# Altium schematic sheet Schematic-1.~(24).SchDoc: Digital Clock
size A3; Author: DENANATH S; DrawnBy: DENANATH; Revision: 1; SheetNumber: 1; SheetTotal: 1
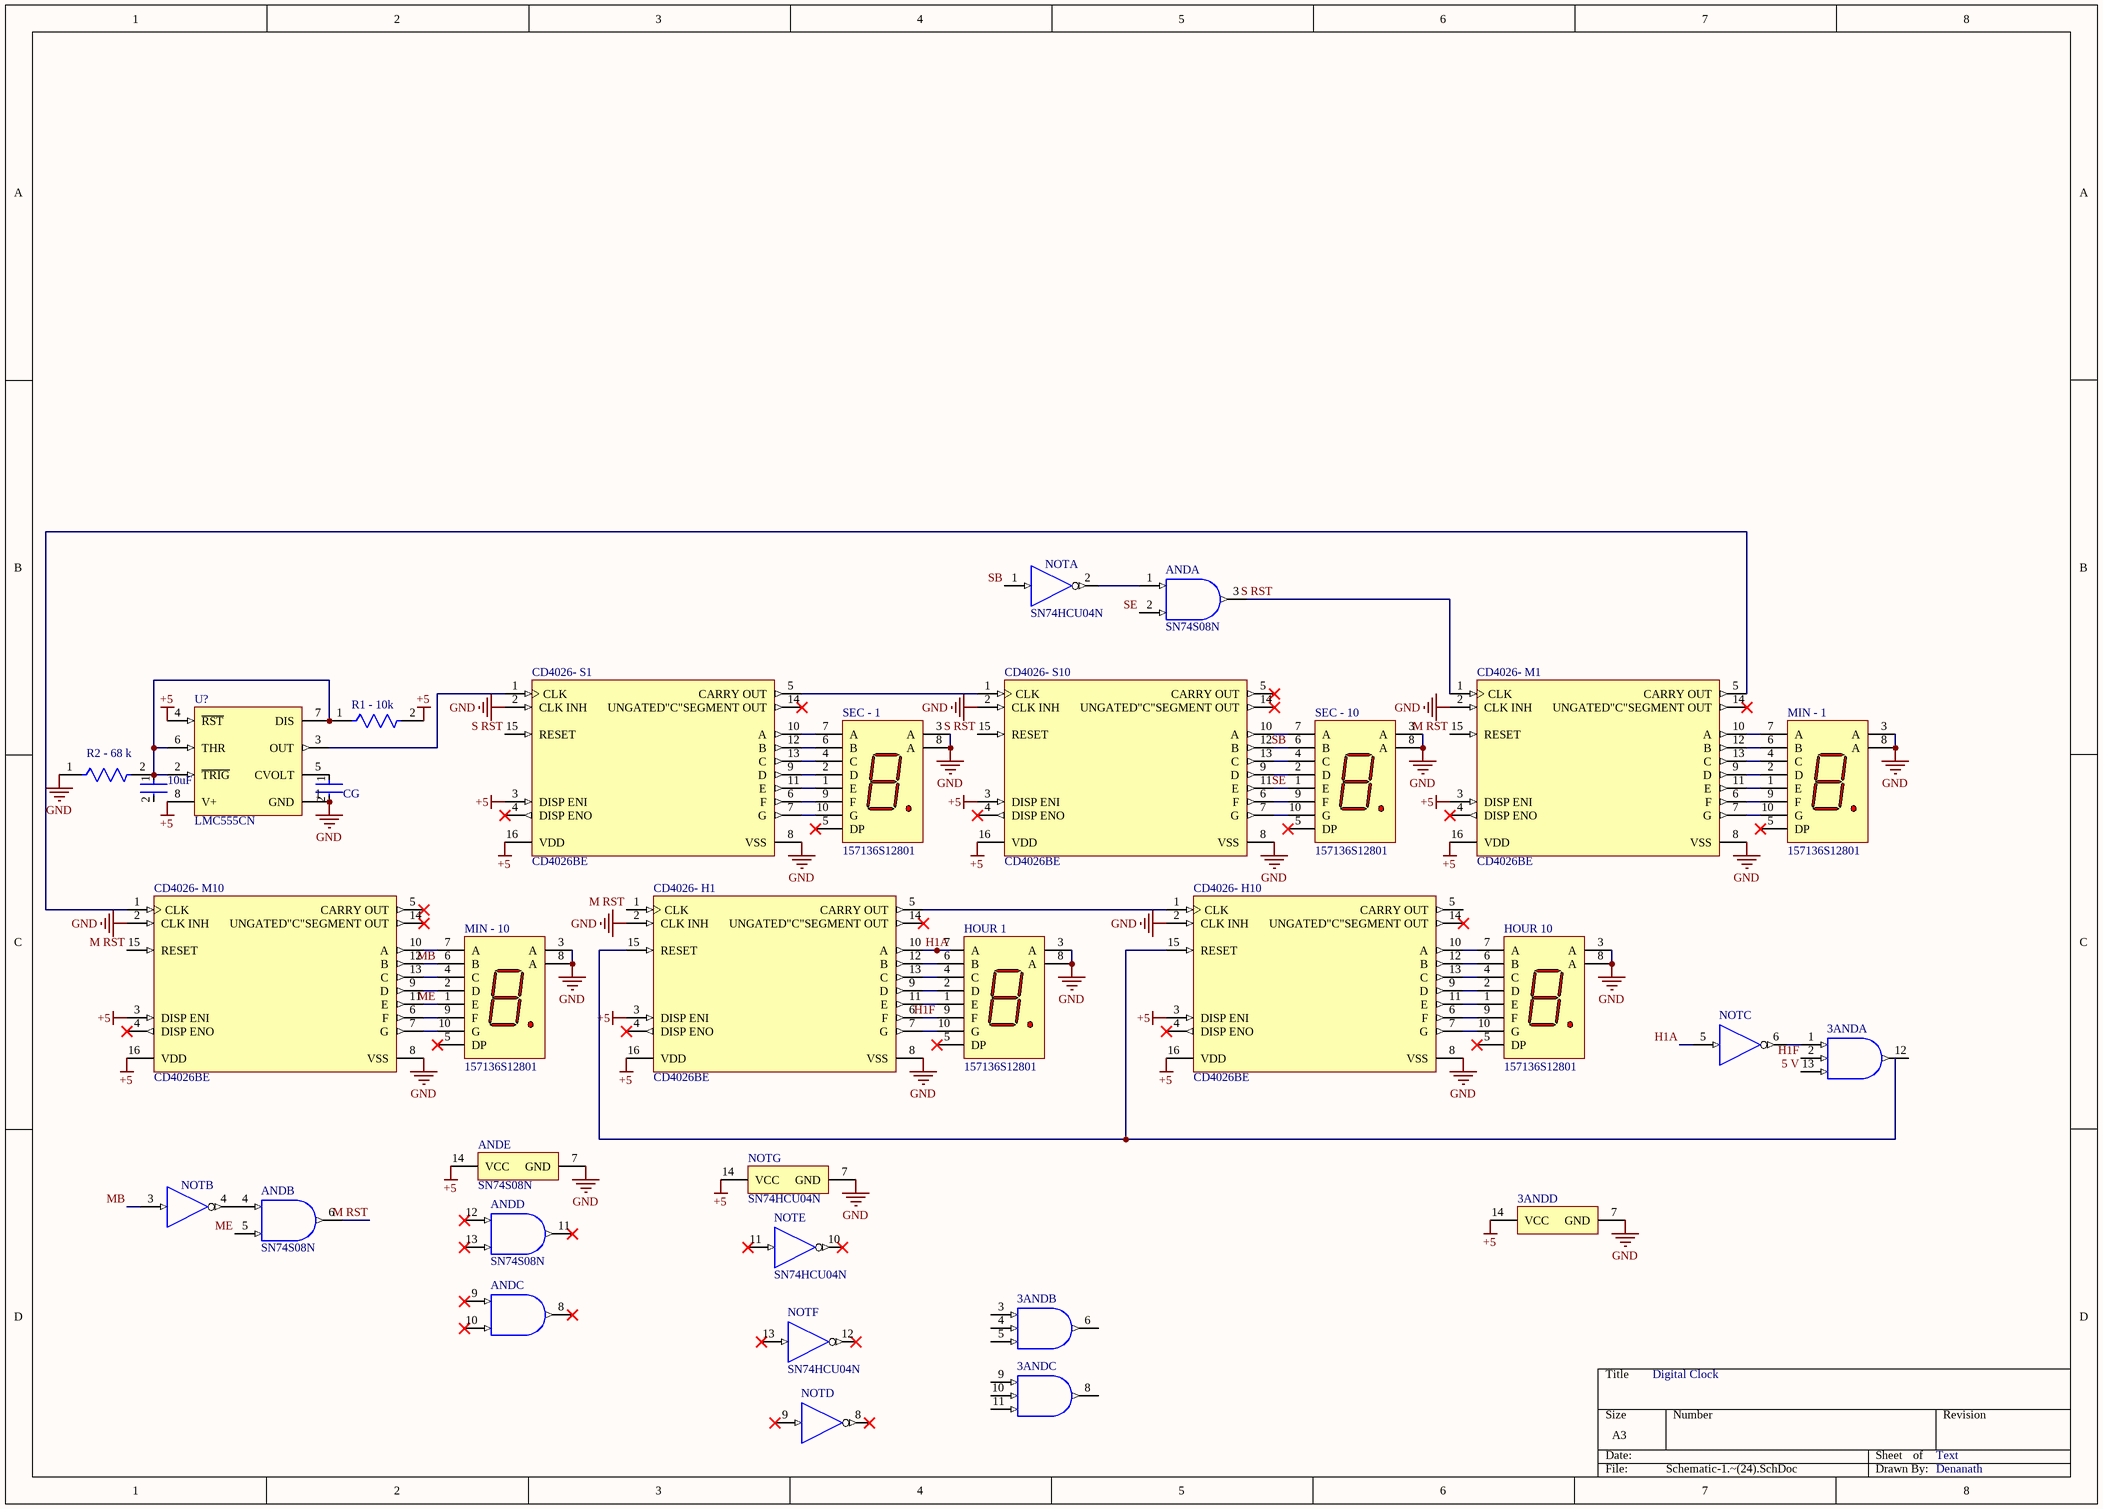
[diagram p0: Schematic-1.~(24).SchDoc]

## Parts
3AND  SN74LS11N  [N0014A]  (value not drawn)  (parts A,B,C,D of 4)
10uF  VY1472M63Y5UQ6TV0  [FP-VY1472M63Y5UQ6TV0-MFG]  (value not drawn)
AND  SN74S08N  [N0014A]  (parts A,B,C,D,E of 5)
CD4026-_H1  CD4026BE  [N0016A]
CD4026-_H10  CD4026BE  [N0016A]
CD4026-_M1  CD4026BE  [N0016A]
CD4026-_M10  CD4026BE  [N0016A]
CD4026-_S1  CD4026BE  [N0016A]
CD4026-_S10  CD4026BE  [N0016A]
CG  VY1472M63Y5UQ6TV0  [FP-VY1472M63Y5UQ6TV0-MFG]  (value not drawn)
HOUR_1  157136S12801  [WL-T7DS_L17.5W12.4H7]
HOUR_10  157136S12801  [WL-T7DS_L17.5W12.4H7]
MIN_-_1  157136S12801  [WL-T7DS_L17.5W12.4H7]
MIN_-_10  157136S12801  [WL-T7DS_L17.5W12.4H7]
NOT  SN74HCU04N  [N0014A]  (parts A,B,C,D,E,F,G of 7)
R1_-_10k  VR37000001204JA100  [FP-VR37-MFG]  (value not drawn)
R2_-_68_k  VR37000001204JA100  [FP-VR37-MFG]  (value not drawn)
SEC_-_1  157136S12801  [WL-T7DS_L17.5W12.4H7]
SEC_-_10  157136S12801  [WL-T7DS_L17.5W12.4H7]
U?  LMC555CN  [P0008A]

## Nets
+5: 3AND.14(VCC) AND.14(VCC) CD4026-_H1.3(DISP_ENI) CD4026-_H1.16(VDD) CD4026-_H10.3(DISP_ENI) CD4026-_H10.16(VDD) CD4026-_M1.3(DISP_ENI) CD4026-_M1.16(VDD) CD4026-_M10.3(DISP_ENI) CD4026-_M10.16(VDD) CD4026-_S1.3(DISP_ENI) CD4026-_S1.16(VDD) CD4026-_S10.3(DISP_ENI) CD4026-_S10.16(VDD) NOT.14(VCC) R1_-_10k.2 U?.4(~{RST}) U?.8(V+)
GND: 3AND.7(GND) AND.7(GND) CD4026-_H1.2(CLK_INH) CD4026-_H1.8(VSS) CD4026-_H10.2(CLK_INH) CD4026-_H10.8(VSS) CD4026-_M1.2(CLK_INH) CD4026-_M1.8(VSS) CD4026-_M10.2(CLK_INH) CD4026-_M10.8(VSS) CD4026-_S1.2(CLK_INH) CD4026-_S1.8(VSS) CD4026-_S10.2(CLK_INH) CD4026-_S10.8(VSS) CG.2 HOUR_1.3(A) HOUR_1.8(A) HOUR_10.3(A) HOUR_10.8(A) MIN_-_1.3(A) MIN_-_1.8(A) MIN_-_10.3(A) MIN_-_10.8(A) NOT.7(GND) R2_-_68_k.1 SEC_-_1.3(A) SEC_-_1.8(A) SEC_-_10.3(A) SEC_-_10.8(A) U?.1(GND)
5 V: 3AND.13(1C)
H1A: CD4026-_H1.10(A) HOUR_1.7(A) NOT.5(3A)
H1F: 3AND.2(1B) CD4026-_H1.6(F) HOUR_1.9(F)
M RST: AND.6(2Y) CD4026-_H1.1(CLK) CD4026-_M1.15(RESET) CD4026-_M10.15(RESET)
MB: CD4026-_M10.12(B) MIN_-_10.6(B) NOT.3(2A)
ME: AND.5(2B) CD4026-_M10.11(E) MIN_-_10.1(E)
S RST: AND.3(1Y) CD4026-_M1.1(CLK) CD4026-_S1.15(RESET) CD4026-_S10.15(RESET)
SB: CD4026-_S10.12(B) NOT.1(1A) SEC_-_10.6(B)
SE: AND.2(1B) CD4026-_S10.11(E) SEC_-_10.1(E)
Net3AND_1: 3AND.1(1A) NOT.6(~{3Y})
Net10uF_1: 10uF.1 R1_-_10k.1 R2_-_68_k.2 U?.2(~{TRIG}) U?.6(THR) U?.7(DIS)
NetAND_1: AND.1(1A) NOT.2(~{1Y})
NetAND_4: AND.4(2A) NOT.4(~{2Y})
NetCD4026-_H1_5: CD4026-_H1.5(CARRY_OUT) CD4026-_H10.1(CLK)
NetCD4026-_H1_7: CD4026-_H1.7(G) HOUR_1.10(G)
NetCD4026-_H1_9: CD4026-_H1.9(D) HOUR_1.2(D)
NetCD4026-_H1_11: CD4026-_H1.11(E) HOUR_1.1(E)
NetCD4026-_H1_12: CD4026-_H1.12(B) HOUR_1.6(B)
NetCD4026-_H1_13: CD4026-_H1.13(C) HOUR_1.4(C)
NetCD4026-_H1_15: CD4026-_H1.15(RESET) CD4026-_H10.15(RESET)
NetCD4026-_H10_6: CD4026-_H10.6(F) HOUR_10.9(F)
NetCD4026-_H10_7: CD4026-_H10.7(G) HOUR_10.10(G)
NetCD4026-_H10_9: CD4026-_H10.9(D) HOUR_10.2(D)
NetCD4026-_H10_10: CD4026-_H10.10(A) HOUR_10.7(A)
NetCD4026-_H10_11: CD4026-_H10.11(E) HOUR_10.1(E)
NetCD4026-_H10_12: CD4026-_H10.12(B) HOUR_10.6(B)
NetCD4026-_H10_13: CD4026-_H10.13(C) HOUR_10.4(C)
NetCD4026-_M1_5: CD4026-_M1.5(CARRY_OUT) CD4026-_M10.1(CLK)
NetCD4026-_M1_6: CD4026-_M1.6(F) MIN_-_1.9(F)
NetCD4026-_M1_7: CD4026-_M1.7(G) MIN_-_1.10(G)
NetCD4026-_M1_9: CD4026-_M1.9(D) MIN_-_1.2(D)
NetCD4026-_M1_10: CD4026-_M1.10(A) MIN_-_1.7(A)
NetCD4026-_M1_11: CD4026-_M1.11(E) MIN_-_1.1(E)
NetCD4026-_M1_12: CD4026-_M1.12(B) MIN_-_1.6(B)
NetCD4026-_M1_13: CD4026-_M1.13(C) MIN_-_1.4(C)
NetCD4026-_M10_6: CD4026-_M10.6(F) MIN_-_10.9(F)
NetCD4026-_M10_7: CD4026-_M10.7(G) MIN_-_10.10(G)
NetCD4026-_M10_9: CD4026-_M10.9(D) MIN_-_10.2(D)
NetCD4026-_M10_10: CD4026-_M10.10(A) MIN_-_10.7(A)
NetCD4026-_M10_13: CD4026-_M10.13(C) MIN_-_10.4(C)
NetCD4026-_S1_1: CD4026-_S1.1(CLK) U?.3(OUT)
NetCD4026-_S1_5: CD4026-_S1.5(CARRY_OUT) CD4026-_S10.1(CLK)
NetCD4026-_S1_6: CD4026-_S1.6(F) SEC_-_1.9(F)
NetCD4026-_S1_7: CD4026-_S1.7(G) SEC_-_1.10(G)
NetCD4026-_S1_9: CD4026-_S1.9(D) SEC_-_1.2(D)
NetCD4026-_S1_10: CD4026-_S1.10(A) SEC_-_1.7(A)
NetCD4026-_S1_11: CD4026-_S1.11(E) SEC_-_1.1(E)
NetCD4026-_S1_12: CD4026-_S1.12(B) SEC_-_1.6(B)
NetCD4026-_S1_13: CD4026-_S1.13(C) SEC_-_1.4(C)
NetCD4026-_S10_6: CD4026-_S10.6(F) SEC_-_10.9(F)
NetCD4026-_S10_7: CD4026-_S10.7(G) SEC_-_10.10(G)
NetCD4026-_S10_9: CD4026-_S10.9(D) SEC_-_10.2(D)
NetCD4026-_S10_10: CD4026-_S10.10(A) SEC_-_10.7(A)
NetCD4026-_S10_13: CD4026-_S10.13(C) SEC_-_10.4(C)
NetCG_1: CG.1 U?.5(CVOLT)

Not connected (* = marked no-connect by the designer): 3AND 3(2A) 4(2B) 5(2C) 6(2Y) 8(3Y) 9(3A) 10(3B) 11(3C) 12(1Y); 10uF 2; AND 8(3Y)* 9(3A)* 10(3B)* 11(4Y)* 12(4A)* 13(4B)*; CD4026-_H1 4(DISP_ENO)* 14(UNGATED"C"SEGMENT_OUT)*; CD4026-_H10 4(DISP_ENO)* 5(CARRY_OUT) 14(UNGATED"C"SEGMENT_OUT)*; CD4026-_M1 4(DISP_ENO)* 14(UNGATED"C"SEGMENT_OUT)*; CD4026-_M10 4(DISP_ENO)* 5(CARRY_OUT)* 14(UNGATED"C"SEGMENT_OUT)*; CD4026-_S1 4(DISP_ENO)* 14(UNGATED"C"SEGMENT_OUT)*; CD4026-_S10 4(DISP_ENO)* 5(CARRY_OUT)* 14(UNGATED"C"SEGMENT_OUT)*; HOUR_1 5(DP)*; HOUR_10 5(DP)*; MIN_-_1 5(DP)*; MIN_-_10 5(DP)*; NOT 8(~{4Y})* 9(4A)* 10(~{5Y})* 11(5A)* 12(~{6Y})* 13(6A)*; SEC_-_1 5(DP)*; SEC_-_10 5(DP)*

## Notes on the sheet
- Digital Clock
- Text
- Denanath

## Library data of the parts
3AND = CMP-0777-00254-3: Triple 3-input positive-AND gates, N0014A, TUBE; Manufacturer: Texas Instruments; Output Type: TTL; VCC(Min)(V): 4.75; Technology Family: LS; Bits(#): 3; Voltage(Nom)(V): 5; ICC @ Nom Voltage(Max)(mA): 0.0036; Rating: Catalog; VCC(Max)(V): 5.25; tpd @ Nom Voltage(Max)(ns): 15; Output Drive (IOL/IOH)(Max)(mA): 0/8; F @ Nom Voltage(Max)(Mhz): 35; Schmitt Trigger: No
10uF CG = CMP-02417-000050-1: CAP CER 4700PF 760VAC Y5U RADIAL; Voltage Rating (AC): 500V; Lead Diameter: 0.6mm; Capacitance: 4.7nF; Tolerance: 20%; Lead/Base Style: Kinked
AND = CMP-0777-00282-3: Quad 2-input positive-AND gates, N0014A, TUBE; Manufacturer: Texas Instruments; Output Drive (IOL/IOH)(Max)(mA): -24/24; Rating: Catalog; VCC(Min)(V): 4.75; Bits(#): 4; Input Type: TTL; Schmitt Trigger: No; tpd @ Nom Voltage(Max)(ns): 7.5; Technology Family: S; Voltage(Nom)(V): 5; VCC(Max)(V): 5.25; F @ Nom Voltage(Max)(Mhz): 50; ICC @ Nom Voltage(Max)(mA): 0.032
CD4026-_H1 CD4026-_H10 CD4026-_M1 CD4026-_M10 CD4026-_S1 CD4026-_S10 = CMP-1623-00561-2: CMOS Decade Counter/Divider with Decoded 7-Segment Display Outputs and Display Enable, N0016A, TUBE; Manufacturer: Texas Instruments; ICC @ Nom Voltage(Max)(mA): 0.03; tpd @ Nom Voltage(Max)(ns): 250; F @ Nom Voltage(Max)(Mhz): 8; Bits(#): 7; VCC(Max)(V): 18; VCC(Min)(V): 3; Output Drive (IOL/IOH)(Max)(mA): 1.5/-1.5; Inputs: 1; Rating: Catalog; Technology Family: CD4000; Schmitt Trigger: No; Voltage(Nom)(V): 5,10,15
HOUR_1 HOUR_10 MIN_-_1 MIN_-_10 SEC_-_1 SEC_-_10 = CMP-03913-119893999-3: 7-Seg Display, Comm Anode, Super Red Rohs Compliant: Yes; Forward Voltage: 2V; Dominant Wavelength: 635nm; Max Reverse Voltage (DC): 5V; Forward Current: 100mA; Luminous Intensity: 20mcd
NOT = CMP-1615-00910-2: Hex Inverters, N0014A, TUBE; Manufacturer: Texas Instruments; Technology Family: HC; Bits(#): 6; Schmitt Trigger: No; Output Drive (IOL/IOH)(Max)(mA): -4/4; Input Type: CMOS; F @ Nom Voltage(Max)(Mhz): 20; VCC(Min)(V): 2; Voltage(Nom)(V): 5; ICC @ Nom Voltage(Max)(mA): 0.02; Rating: Catalog
R1_-_10k R2_-_68_k = CMP-02408-000054-1: RES 1.2M OHM 5% 1/2W AXIAL; Voltage Rating: 3.5kV; Power Rating: 500mW; Temperature Coefficient: 200ppm/°C; Resistance: 1.2MR
U? = CMP-0056-00035-3: CMOS Timer, 8-pin MDIP; Manufacturer: Texas Instruments; PowerWise: N; CompType: Analog IC; PackageTopMarking: NSUZXYTTE#*LMC*555CN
